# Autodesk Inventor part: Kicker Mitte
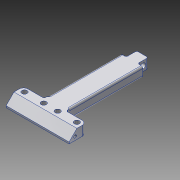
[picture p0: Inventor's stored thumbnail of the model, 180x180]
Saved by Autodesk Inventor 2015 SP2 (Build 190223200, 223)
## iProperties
Created: 2015-08
Part Number: Kicker Mitte
Material: Aluminium 6061
Document SubType Name: Modeling
Designer: rYan
Mass: 9.73635 g
Surface Area: 21.2862 cm^2
Volume: 3.60605 cm^3
Density: 2.7 g/cm^3
Appearance: Aluminium - flach
Author: rYan
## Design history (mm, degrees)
sketch "Skizze5"
  geometry: L1 (6.25, 44)-(6.25, 0); L2 (-6.25, 0)-(-6.25, 44); L3 (3.25, 44)-(3.25, 50); L4 (3.25, 50)-(-3.25, 50); L5 (-3.25, 50)-(-3.25, 44); L6 (18, 0)-(18, -10); L7 (18, -10)-(-18, -10); L8 (-18, -10)-(-18, 0); L9 (0, 62)-(0, -22) reference; L10 (-25.2, 0)-(25.2, 0) reference; L11 (-6.25, 44)-(-3.25, 44); L12 (3.25, 44)-(6.25, 44); L13 (-18, 0)-(-6.25, 0); L14 (18, 0)-(6.25, 0); 1 further point
  constraints: 24 end point, 5 parallel, 2 horizontal, 2 perpendicular, 2 point on line, 5 other
  dimensions: "d24" = 12.5 distance between parallel lines of L1 L2; "d27" = 6.5 distance of L3.end L4.end; "d28" = 6 distance of L3.start L3.end; "d49" = 0 distance between parallel lines of L13 L10; "d50" = 10 distance of L7.end L8.end; "d51" = 44 distance between parallel lines of L12 L10; "d52" = 36 distance of L6.end L7.end
extrude "Extrusion3" new body sketch "Skizze5" stored distance "d30" = 5.5; taper "d31" = 0 deg
sketch "Skizze6"
  geometry: L1 (5.5, 6)-(0, 6) reference; L2 (0, 0)-(0, 6) reference; L3 (5.5, 0)-(0, 0) reference; L4 (5.5, 6)-(5.5, 0) reference; L5 (0, 0)-(0, 6) reference; L6 (0, 3)-(5.5, 3); L7 (5.5, 0)-(5.5, 6) reference; 2 further points
  constraints: 3 midpoint, 2 end point, 1 horizontal
  dimensions: "d32" = 3 distance between parallel lines of L1 L6
hole "Bohrung3" sketch "Skizze6" at (2.75, 3) diameter "d33" = 3; stored, may be unused: countersink angle "d37" = 90 deg, drill point angle "d39" = 118 deg; dims "d34" = 6, "d35" = 4, "d36" = 2, "d38" = 8
sketch "Skizze7"
  geometry: L1 (-6.25, 44)-(-6.25, 0) reference; L2 (-18, 0)-(-18, -10) reference; L3 (-18, -10)-(18, -10) reference; L4 (18, -10)-(18, 0) reference; L5 (6.25, 0)-(6.25, 44) reference; L6 (6.25, 44)-(3.25, 44) reference; L7 (3.25, 44)-(3.25, 50) reference; L8 (3.25, 50)-(-3.25, 50) reference; L9 (-3.25, 50)-(-3.25, 44) reference; L10 (-3.25, 44)-(-6.25, 44) reference; L11 (-18, 0)-(-18, -10) reference; L12 (-18, -2.5)-(18, -2.5); L13 (0, 62)-(0, -22) reference; L14 (-28, 0)-(28, 0) reference; L15 (18, 0)-(6.25, 0) reference; L16 (-6.25, 0)-(-18, 0) reference; 6 further points
  constraints: 6 point on line, 2 end point, 2 symmetric about line, 1 perpendicular
  dimensions: "d41" = 30 distance of point (15, -2.5) point (-15, -2.5); "d58" = 2.5 distance between parallel lines of L16 L12; "d69" = 8 distance of point (4, -2.5) point (-4, -2.5)
hole "Bohrung4" sketch "Skizze7" at (-15, -2.5), (15, -2.5), (-4, -2.5), (4, -2.5) diameter "d42" = 3; stored, may be unused: countersink angle "d46" = 90 deg, drill point angle "d48" = 118 deg; dims "d43" = 6, "d44" = 4, "d45" = 2, "d47" = 8
chamfer "Fase1" distance "d54" = 4.5; stored, may be unused: second distance "d55" = 2, angle "d56" = 30 deg
fillet "Rundung1" dims "d59" = 2.5
sketch "Skizze8"
  geometry: L1 (1, 7.5)-(1, 0) reference; L2 (-4.5, 7.5)-(1, 7.5) reference; 3 further points
  dimensions: "d60" = 2 distance from line of point (-1, 3.5) L1; "d61" = 4 distance from line of point (-1, 3.5) L2
hole "Bohrung5" sketch "Skizze8" at (-1, 3.5) diameter "d62" = 1.567; stored, may be unused: countersink angle "d66" = 90 deg, drill point angle "d68" = 118 deg; dims "d63" = 4, "d64" = 4, "d65" = 2, "d67" = 4
mirror "Spiegeln1"
fillet "Fillet2" dims "d70" = 1
fillet "Rundung3" dims "d71" = 0, "d72" = 1, "d73" = 1, "d74" = 0.6, "d79" = 0, "d80" = 0.3
fillet "Rundung4" dims "d75" = 1, "d76" = 0, "d77" = 1, "d78" = 9.4, "d81" = 0, "d82" = 9.7
mirror "Spiegeln2"
fillet "Rundung5" dims "d83" = 1
node "Volumenkörper2"
node "Projizierte Kontur4"
node "Projizierte Kontur5"
